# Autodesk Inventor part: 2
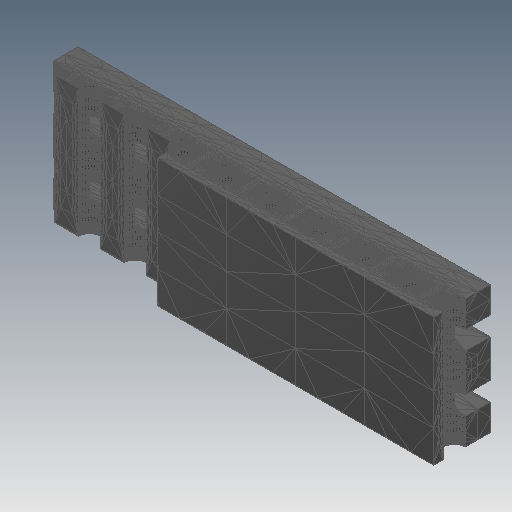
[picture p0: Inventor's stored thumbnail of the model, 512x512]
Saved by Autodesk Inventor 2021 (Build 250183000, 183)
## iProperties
Created: 2026-04
Part Number: 2
Material: Generic
Document SubType Name: Modeling
Designer: JCBG
Density: 1 g/cm^3
Appearance: Default
Author: JCBG
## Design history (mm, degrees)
node "2"
  node "MeshFeature1"
